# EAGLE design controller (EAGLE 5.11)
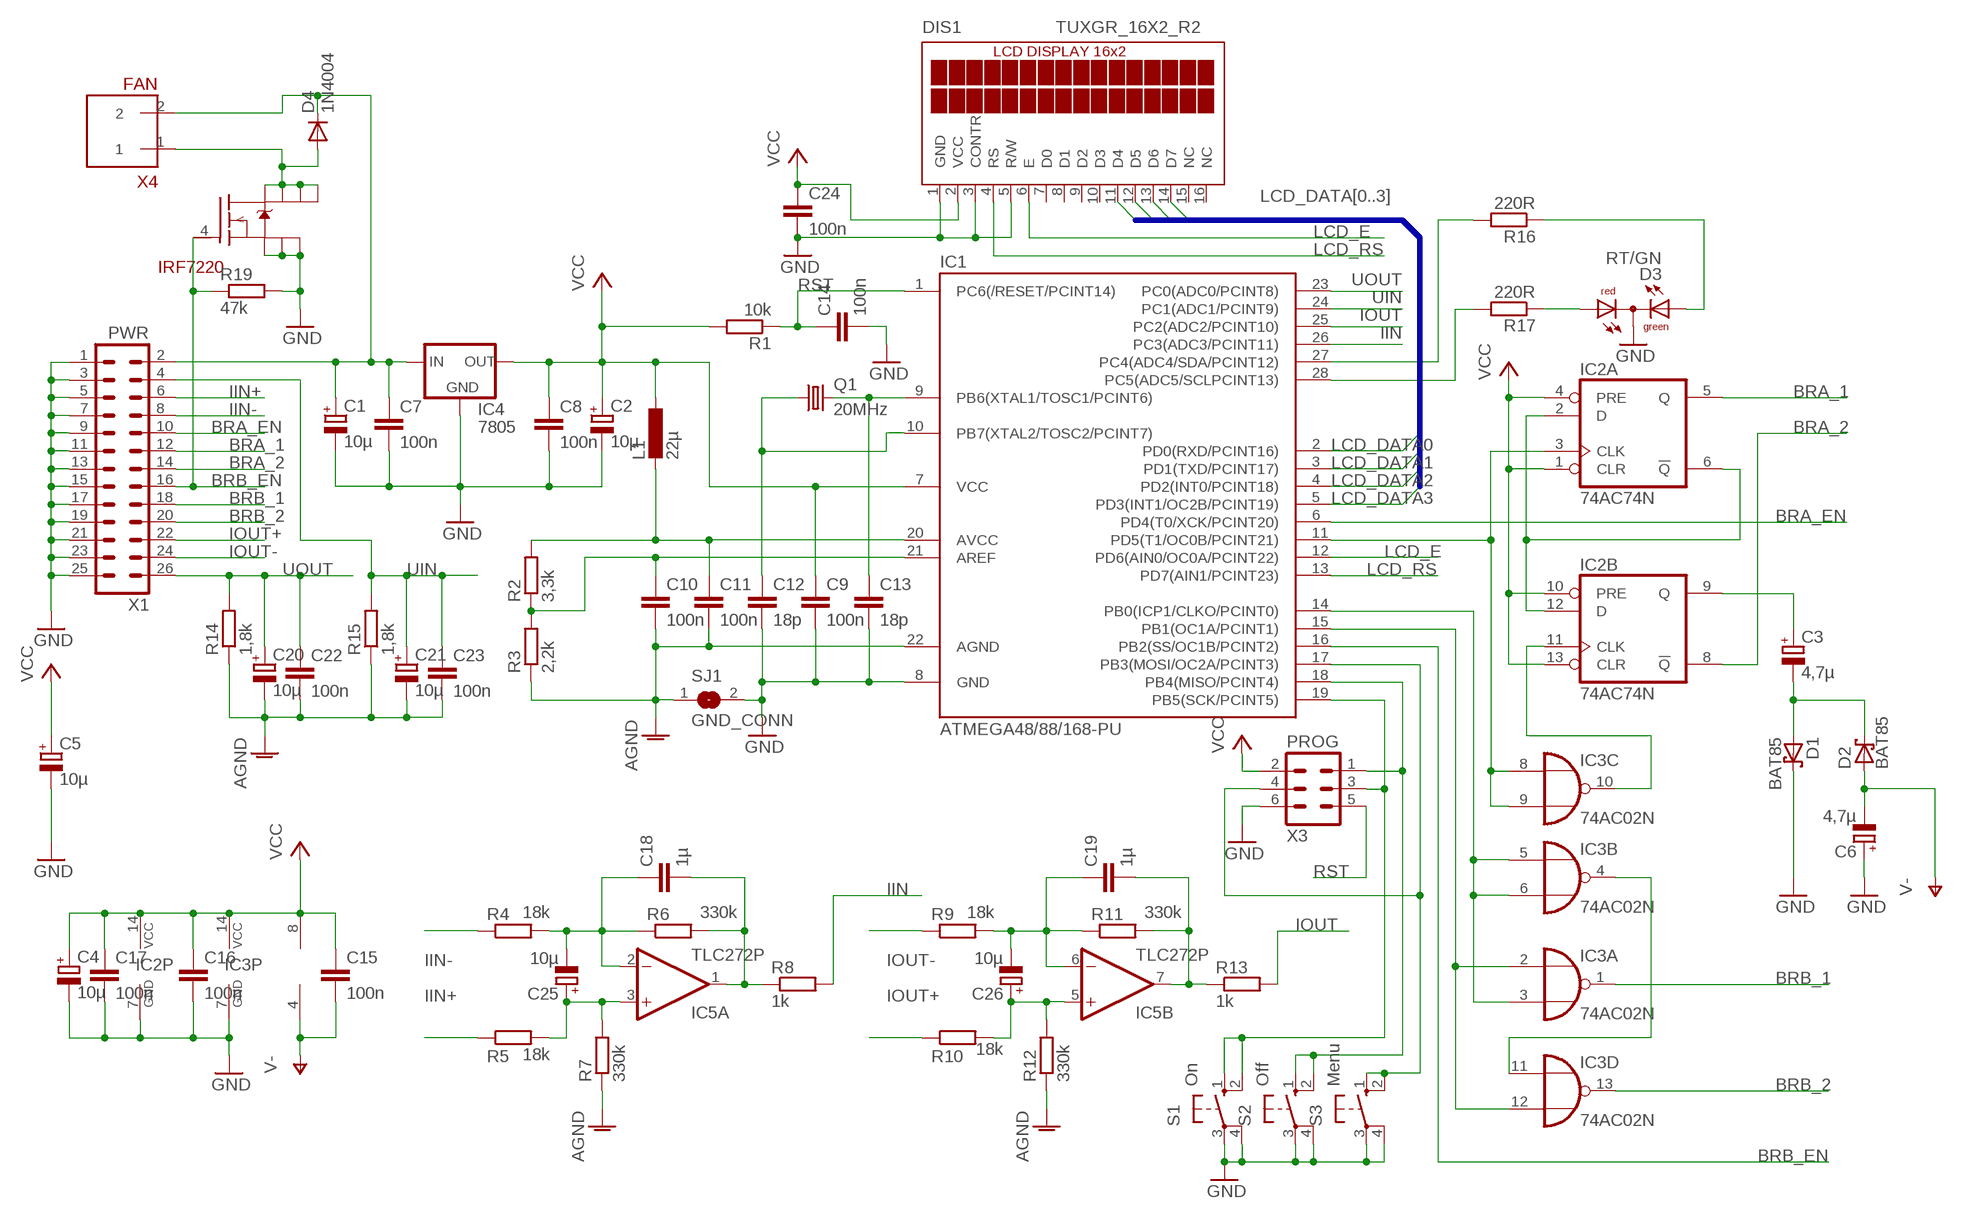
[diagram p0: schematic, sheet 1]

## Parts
C1  10µ  CPOL-EUE2.5-5  [E2,5-5]
C2  10µ  CPOL-EUE2.5-5  [E2,5-5]
C3  4,7µ  CPOL-EUE2.5-5  [E2,5-5]
C4  10µ  CPOL-EUE2.5-5  [E2,5-5]
C5  10µ  CPOL-EUE2.5-5  [E2,5-5]
C6  4,7µ  CPOL-EUE2.5-5  [E2,5-5]
C7  100n  C-EU025-024X044  [C025-024X044]
C8  100n  C-EU025-024X044  [C025-024X044]
C9  100n  C-EU025-024X044  [C025-024X044]
C10  100n  C-EU025-024X044  [C025-024X044]
C11  100n  C-EU025-024X044  [C025-024X044]
C12  18p  C-EU025-024X044  [C025-024X044]
C13  18p  C-EU025-024X044  [C025-024X044]
C14  100n  C-EU025-024X044  [C025-024X044]
C15  100n  C-EU025-024X044  [C025-024X044]
C16  100n  C-EU025-024X044  [C025-024X044]
C17  100n  C-EU025-024X044  [C025-024X044]
C18  1µ  C-EU050-050X075  [C050-050X075]
C19  1µ  C-EU050-050X075  [C050-050X075]
C20  10µ  CPOL-EUE2.5-5  [E2,5-5]
C21  10µ  CPOL-EUE2.5-5  [E2,5-5]
C22  100n  C-EU025-024X044  [C025-024X044]
C23  100n  C-EU025-024X044  [C025-024X044]
C24  100n  C-EU025-024X044  [C025-024X044]
C25  10µ  CPOL-EUE2.5-5  [E2,5-5]
C26  10µ  CPOL-EUE2.5-5  [E2,5-5]
D1  BAT85  BAT42  [DO35-10]
D2  BAT85  BAT42  [DO35-10]
D3  RT/GN  DUOLED5MM  [DUOLED5MM]
D4  1N4004  [DO41-10]
DIS1  TUXGR_16X2_R2  [TUXGR_16X2_R2]
IC1  ATMEGA48/88/168-PU  [DIL28-3]
IC2  74AC74N  [DIL14]
IC3  74AC02N  [DIL14]
IC4  7805  78XXL  [78XXL]
IC5  TLC272P  [DIL08]
L1  22µ  L-EU0207/12  [0207/12]
Q1  20MHz  CRYSTALHC49U-V  [HC49U-V]
R1  10k  R-EU_0207/10  [0207/10]
R2  3,3k  R-EU_0207/10  [0207/10]
R3  2,2k  R-EU_0207/10  [0207/10]
R4  18k  R-EU_0207/10  [0207/10]
R5  18k  R-EU_0207/10  [0207/10]
R6  330k  R-EU_0207/10  [0207/10]
R7  330k  R-EU_0207/10  [0207/10]
R8  1k  R-EU_0207/10  [0207/10]
R9  18k  R-EU_0207/10  [0207/10]
R10  18k  R-EU_0207/10  [0207/10]
R11  330k  R-EU_0207/10  [0207/10]
R12  330k  R-EU_0207/10  [0207/10]
R13  1k  R-EU_0207/10  [0207/10]
R14  1,8k  R-EU_0207/10  [0207/10]
R15  1,8k  R-EU_0207/10  [0207/10]
R16  220R  R-EU_0207/10  [0207/10]
R17  220R  R-EU_0207/10  [0207/10]
R19  47k  R-EU_0207/10  [0207/10]
S1  On  10-XX  [B3F-10XX]
S2  Off  10-XX  [B3F-10XX]
S3  Menu  10-XX  [B3F-10XX]
SJ1  GND_CONN  SJ  [SJ]
T1  IRF7413  [SO-8]
X1  PWR  ML26  [ML26]
X3  PROG  ML6  [ML6]
X4  FAN  KLEMME2X5  [KLEMME2X5]

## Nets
AGND: C10.2 C11.2 C20.- C21.- C22.2 C23.2 IC1.22(AGND) R3.1 R7.1 R12.1 R14.1 R15.1 SJ1.1
BRA_1: IC2.5(A:Q) X1.12
BRA_2: IC2.8(B:!Q) X1.14
BRA_EN: IC1.6(PD4(T0/XCK/PCINT20)) X1.10
BRB_1: IC3.1(A:O) X1.18
BRB_2: IC3.13(D:O) X1.20
BRB_EN: IC1.16(PB2(SS/OC1B/PCINT2)) R19.1 T1.4 X1.16
GND: C1.- C2.- C4.- C5.- C6.+ C7.2 C8.2 C9.2 C12.2 C13.2 C14.2 C16.2 C17.2 C24.2 D1.C D3.K(C) DIS1.1(GND) DIS1.3(CONTR) DIS1.5(R/W) IC1.8(GND) IC2.7(P:GND) IC3.7(P:GND) IC4.GND R19.2 S1.3(P) S1.4(P1) S2.3(P) S2.4(P1) S3.3(P) S3.4(P1) SJ1.2 T1.1 T1.2 T1.3 X1.1 X1.3 X1.5 X1.7 X1.9 X1.11 X1.13 X1.15 X1.17 X1.19 X1.21 X1.23 X1.25 X3.6
IIN: IC1.26(PC3(ADC3/PCINT11)) R8.2
IIN+: R5.1 X1.6
IIN-: R4.1 X1.8
IOUT: IC1.25(PC2(ADC2/PCINT10)) R13.2
IOUT+: R10.1 X1.22
IOUT-: R9.1 X1.24
LCD_DATA0: DIS1.11(D4) IC1.2(PD0(RXD/PCINT16))
LCD_DATA1: DIS1.12(D5) IC1.3(PD1(TXD/PCINT17))
LCD_DATA2: DIS1.13(D6) IC1.4(PD2(INT0/PCINT18))
LCD_DATA3: DIS1.14(D7) IC1.5(PD3(INT1/OC2B/PCINT19))
LCD_E: DIS1.6(E) IC1.12(PD6(AIN0/OC0A/PCINT22))
LCD_RS: DIS1.4(RS) IC1.13(PD7(AIN1/PCINT23))
N$1: C1.+ C7.1 D4.C IC4.IN X1.2 X4.2
N$2: C10.1 IC1.21(AREF) R2.1 R3.2
N$3: C11.1 IC1.20(AVCC) L1.2 R2.2
N$4: IC1.11(PD5(T1/OC0B/PCINT21)) IC2.3(A:CLK) IC3.8(C:I0) IC3.9(C:I1)
N$5: D4.A T1.5 T1.6 T1.7 T1.8 X4.1
N$6: C12.1 IC1.10(PB7(XTAL2/TOSC2/PCINT7)) Q1.1
N$7: C19.2 IC5.7(B:OUT) R11.2 R13.1
N$8: C13.1 IC1.9(PB6(XTAL1/TOSC1/PCINT6)) Q1.2
N$9: IC2.11(B:CLK) IC3.10(C:O)
N$10: IC2.2(A:D) IC2.6(A:!Q) IC2.12(B:D)
N$11: C3.+ IC2.9(B:Q)
N$12: C3.- D1.A D2.C
N$14: C18.1 C25.- IC5.2(A:-IN) R4.2 R6.1
N$15: C18.2 IC5.1(A:OUT) R6.2 R8.1
N$16: C25.+ IC5.3(A:+IN) R5.2 R7.2
N$18: C19.1 C26.- IC5.6(B:-IN) R9.2 R11.1
N$19: C26.+ IC5.5(B:+IN) R10.2 R12.2
N$21: D3.AG R16.1
N$25: IC1.17(PB3(MOSI/OC2A/PCINT3)) S3.1(S) S3.2(S1) X3.4
N$32: IC1.15(PB1(OC1A/PCINT1)) IC3.2(A:I0) IC3.12(D:I1)
N$33: IC1.14(PB0(ICP1/CLKO/PCINT0)) IC3.3(A:I1) IC3.5(B:I0) IC3.6(B:I1)
N$34: IC3.4(B:O) IC3.11(D:I0)
N$35: IC1.18(PB4(MISO/PCINT4)) S2.1(S) S2.2(S1) X3.1
N$36: IC1.19(PB5(SCK/PCINT5)) S1.1(S) S1.2(S1) X3.3
N$37: D3.AR R17.1
N$38: IC1.28(PC5(ADC5/SCLPCINT13)) R17.2
N$39: IC1.27(PC4(ADC4/SDA/PCINT12)) R16.2
RST: C14.1 IC1.1(PC6(/RESET/PCINT14)) R1.1 X3.5
UIN: C21.+ C23.1 IC1.24(PC1(ADC1/PCINT9)) R15.2 X1.4
UOUT: C20.+ C22.1 IC1.23(PC0(ADC0/PCINT8)) R14.2 X1.26
V-: C6.- C15.2 D2.A IC5.4(P:V-)
VCC: C2.+ C4.+ C5.+ C8.1 C9.1 C15.1 C16.1 C17.1 C24.1 DIS1.2(VCC) IC1.7(VCC) IC2.1(A:CLR) IC2.4(A:PRE) IC2.10(B:PRE) IC2.13(B:CLR) IC2.14(P:VCC) IC3.14(P:VCC) IC4.OUT IC5.8(P:V+) L1.1 R1.2 X3.2
Unconnected: DIS1.7(D0) DIS1.8(D1) DIS1.9(D2) DIS1.10(D3) DIS1.15(NC) DIS1.16(NC)

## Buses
LCD_DATA[0..3]

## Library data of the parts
C1-C6 C20 C21 C25 C26 = rcl:CPOL-EU: POLARIZED CAPACITOR, European symbol
C7-C19 C22-C24 = rcl:C-EU: CAPACITOR, European symbol
D1 D2 = diode:BAT42: DIODE
D3 = led:DUOLED5MM: DUO LED 2 colors, 5 mm, round
D4 = diode:1N4004: DIODE
DIS1 = display-lcd:TUXGR_16X2_R2: Tuxgraphics LCD display 16x2 characters reflective, without background light Source: tuxgr_12x2_r2.pdf; OC_FARNELL: unknown; OC_NEWARK: unknown
IC1 = atmega8:ATMEGA48/88/168-PU
IC2 = 74xx-eu:74*74: Dual D type positive edge triggered FLIP FLOP, preset and clear
IC3 = 74xx-eu:74*02: Quad 2-input NOR gate
IC4 = v-reg:78XXL: VOLTAGE REGULATOR
IC5 = linear:TLC272: OP AMP
L1 = rcl:L-EU: INDUCTOR, European symbol
Q1 = andreas:CRYSTAL: CRYSTAL; OC_FARNELL: 1666969; OC_NEWARK: unknown
R1-R17 R19 = rcl:R-EU_: RESISTOR, European symbol
S1-S3 = switch-omron:10-XX: OMRON SWITCH; MPN: B3F-1000; OC_FARNELL: 176432; OC_NEWARK: 36M3542
SJ1 = jumper:SJ: SMD solder JUMPER
T1 = andreas2:IRF7413
X1 = con-ml:ML26: HARTING; OC_FARNELL: unknown; OC_NEWARK: unknown
X3 = con-ml:ML6: HARTING; OC_FARNELL: unknown; OC_NEWARK: unknown
X4 = andreas:KLEMME2X5: Anreihklemme 2-polig, RM5,0

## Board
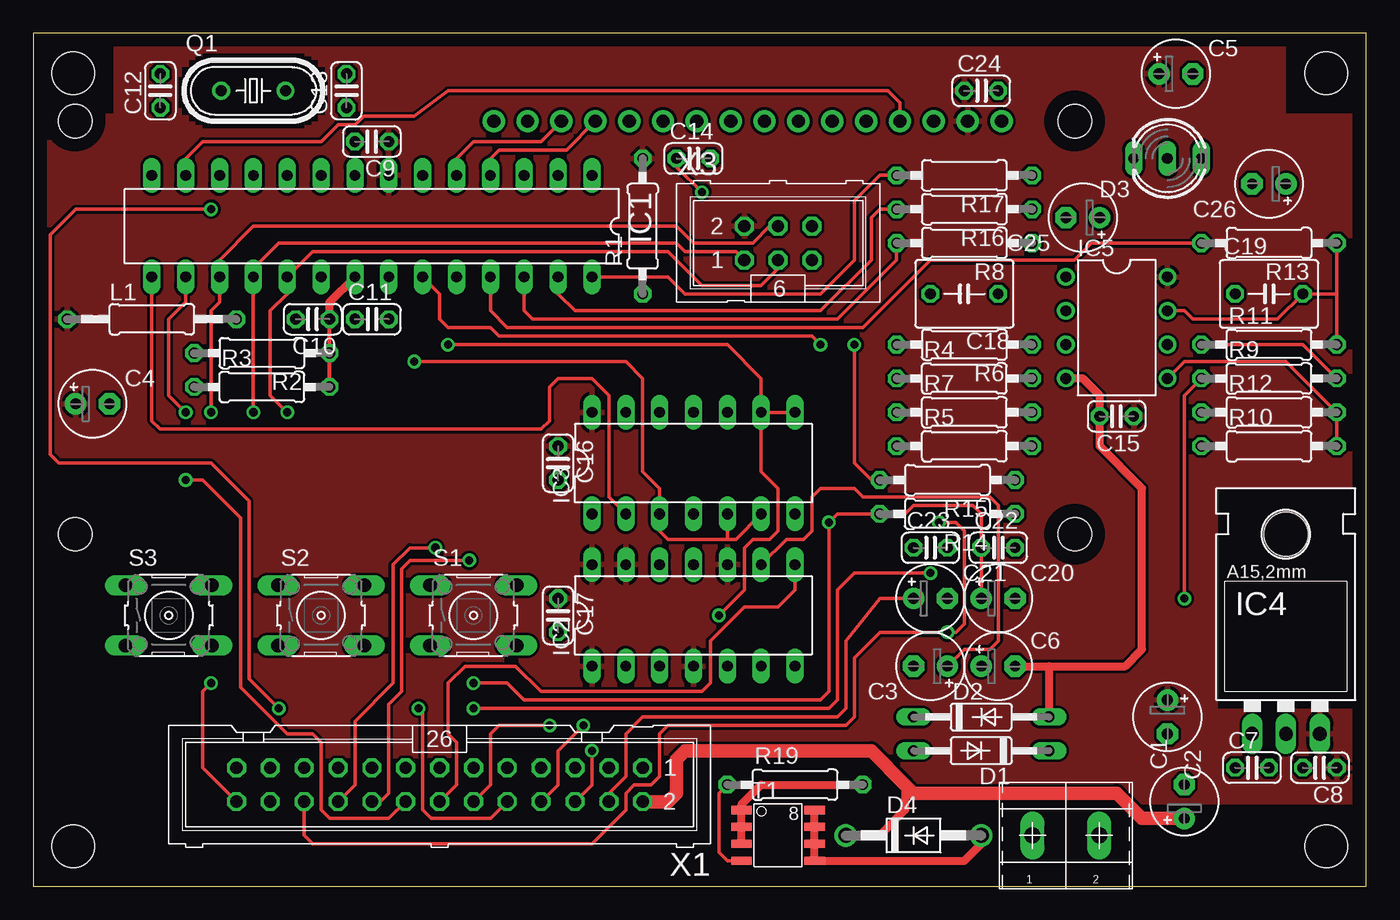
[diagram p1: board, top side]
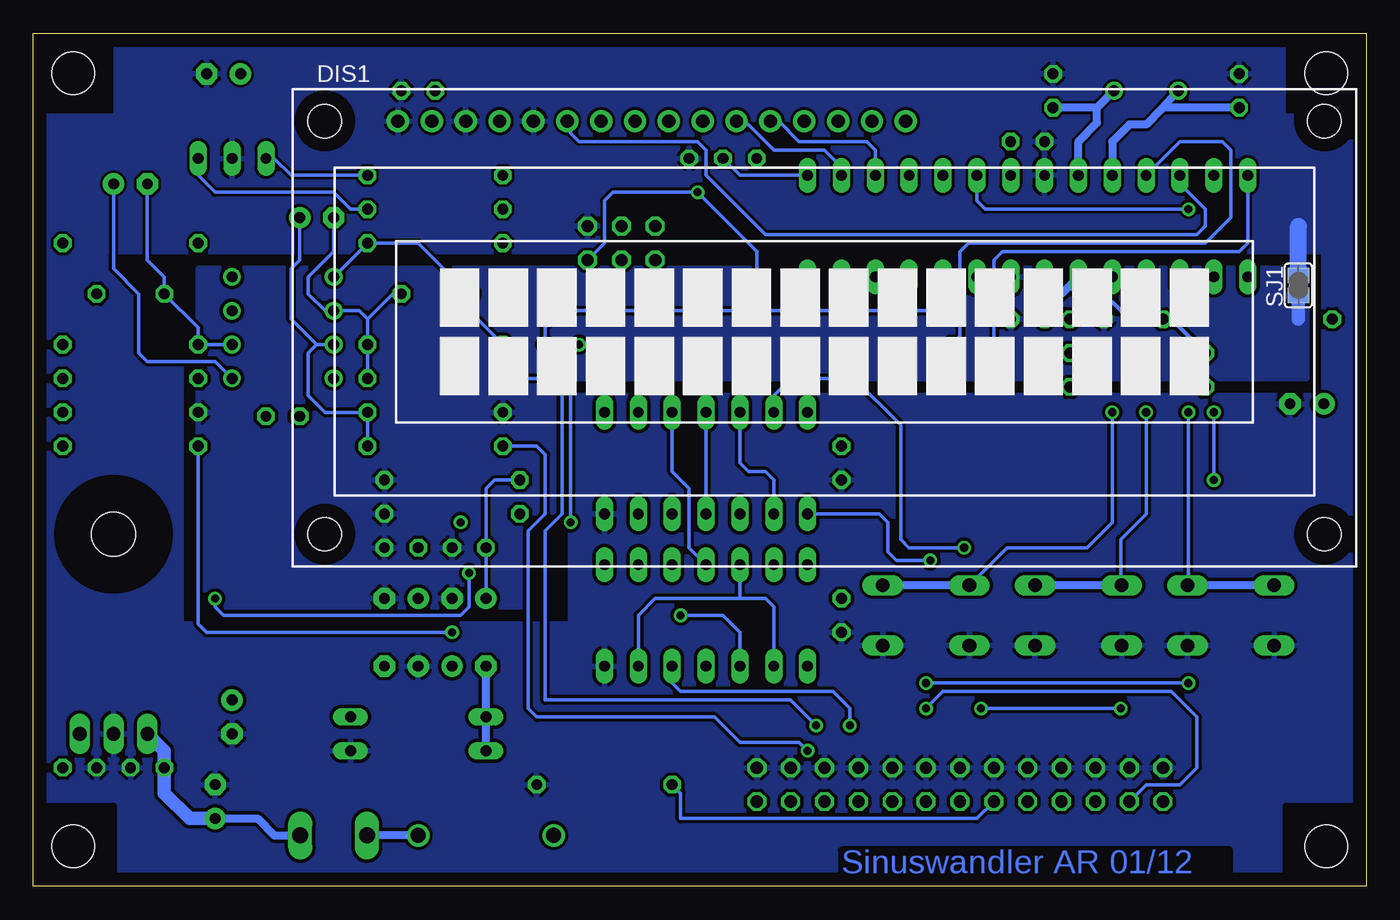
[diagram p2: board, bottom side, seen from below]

Size 100 x 64 mm. Coordinates in mm from the lower left corner, seen from the top.
Outline: 0,0 100,0 100,64 0,64 0,0
Copper layers (1*16): Top 0.035mm / dielectric 1.5mm / Bottom 0.035mm
Design rules "default": minimum track width 10mil, minimum drill 24mil, track to track 8mil, track to pad 8mil, pad to pad 8mil, via to via 8mil, smd to smd 8mil, copper to edge 40mil, drill to drill 8mil, minimum pad ring 10mil, minimum via ring 8mil, stop-mask expansion 4mil, vias tented up to drill 0mil, thermal gap 10mil
Holes 3.2 mm at 3,61 97,61 97,3 3,3
tRestrict: area 88.9,13.3 to 99.1,29.8; area 0,58 to 6,64; area 94,58 to 100,64; area 94,0 to 100,6; area 0,0 to 6,6
bRestrict: area 0,58 to 6,64; area 94,58 to 100,64; area 94,0 to 100,6; area 0,0 to 6,6

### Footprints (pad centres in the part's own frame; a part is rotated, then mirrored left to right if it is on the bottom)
E2,5-5 = drill 0.813 pad 1.6: + -1.27,0 | drill 0.813 pad 1.6 octagon: - 1.27,0
C025-024X044 = drill 0.813 octagon: 1 -1.27,0; 2 1.27,0
C050-050X075 = drill 0.813 octagon: 1 -2.54,0; 2 2.54,0
DO35-10 = drill 0.813 long: A 5.08,0; C -5.08,0
DUOLED5MM = drill 0.813 long: AG -2.54,0; AR 2.54,0; K 0,0
DO41-10 = drill 1.118: A 5.08,0; C -5.08,0
TUXGR_16X2_R2 = drill 1 pad 1.676: 1 -32,15.5; 2 -29.46,15.5; 3 -26.92,15.5; 4 -24.38,15.5; 5 -21.84,15.5; 6 -19.3,15.5; 7 -16.76,15.5; 8 -14.22,15.5; 9 -11.68,15.5; 10 -9.14,15.5; 11 -6.6,15.5; 12 -4.06,15.5; 13 -1.52,15.5; 14 1.02,15.5; 15 3.56,15.5; 16 6.1,15.5 | hole 2.5: -37.5,-15.5; 37.5,-15.5; -37.5,15.5; 37.5,15.5
DIL28-3 = drill 0.813 long: 1 -16.51,-3.81; 2 -13.97,-3.81; 3 -11.43,-3.81; 4 -8.89,-3.81; 5 -6.35,-3.81; 6 -3.81,-3.81; 7 -1.27,-3.81; 8 1.27,-3.81; 9 3.81,-3.81; 10 6.35,-3.81; 11 8.89,-3.81; 12 11.43,-3.81; 13 13.97,-3.81; 14 16.51,-3.81; 15 16.51,3.81; 16 13.97,3.81; 17 11.43,3.81; 18 8.89,3.81; 19 6.35,3.81; 20 3.81,3.81; 21 1.27,3.81; 22 -1.27,3.81; 23 -3.81,3.81; 24 -6.35,3.81; 25 -8.89,3.81; 26 -11.43,3.81; 27 -13.97,3.81; 28 -16.51,3.81
DIL14 = drill 0.813 long: 1 -7.62,-3.81; 2 -5.08,-3.81; 3 -2.54,-3.81; 4 0,-3.81; 5 2.54,-3.81; 6 5.08,-3.81; 7 7.62,-3.81; 8 7.62,3.81; 9 5.08,3.81; 10 2.54,3.81; 11 0,3.81; 12 -2.54,3.81; 13 -5.08,3.81; 14 -7.62,3.81
78XXL = drill 1.016 long: GND 0,-3.81; IN -2.54,-3.81; OUT 2.54,-3.81 | hole 3.302: 0,11.176
DIL08 = drill 0.813 pad 1.27: 1 -3.81,-3.81; 2 -1.27,-3.81; 3 1.27,-3.81; 4 3.81,-3.81; 5 3.81,3.81; 6 1.27,3.81; 7 -1.27,3.81; 8 -3.81,3.81
0207/12 = drill 0.813 octagon: 1 -6.35,0; 2 6.35,0
HC49U-V = drill 0.813: 1 -2.413,0; 2 2.413,0
0207/10 = drill 0.813 octagon: 1 -5.08,0; 2 5.08,0
B3F-10XX = drill 1.016 long: 1 -3.251,2.261; 2 3.251,2.261; 3 -3.251,-2.261; 4 3.251,-2.261
SJ = smd 1.168 x 1.6: 1 -0.762,0; 2 0.762,0
SO-8 = smd 1.524 x 0.61: 1 -2.743,1.27; 2 -2.743,0; 3 -2.743,-1.27; 4 -2.743,-2.54; 5 2.743,-2.54; 6 2.743,-1.27; 7 2.743,0; 8 2.743,1.27
ML26 = drill 0.914 octagon: 1 -15.24,-1.27; 2 -15.24,1.27; 3 -12.7,-1.27; 4 -12.7,1.27; 5 -10.16,-1.27; 6 -10.16,1.27; 7 -7.62,-1.27; 8 -7.62,1.27; 9 -5.08,-1.27; 10 -5.08,1.27; 11 -2.54,-1.27; 12 -2.54,1.27; 13 0,-1.27; 14 0,1.27; 15 2.54,-1.27; 16 2.54,1.27; 17 5.08,-1.27; 18 5.08,1.27; 19 7.62,-1.27; 20 7.62,1.27; 21 10.16,-1.27; 22 10.16,1.27; 23 12.7,-1.27; 24 12.7,1.27; 25 15.24,-1.27; 26 15.24,1.27
ML6 = drill 0.914 octagon: 1 -2.54,-1.27; 2 -2.54,1.27; 3 0,-1.27; 4 0,1.27; 5 2.54,-1.27; 6 2.54,1.27
KLEMME2X5 = drill 1.2 long: 1 0,2.5; 2 0,-2.5

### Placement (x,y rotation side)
C1  86.36,6.35 90 top
C2  85.09,12.7 270 top
C3  67.31,16.51 180 top
C4  4.45,36.2 0 top
C5  85.72,60.96 0 top
C6  72.39,16.51 0 top
C7  91.44,8.89 0 top
C8  96.52,8.89 180 top
C9  25.4,55.88 180 top
C10  20.95,42.55 180 top
C11  25.4,42.55 0 top
C12  9.53,59.69 90 top
C13  23.5,59.69 90 top
C14  49.53,54.61 0 top
C15  81.28,35.26 180 top
C16  39.37,31.75 270 top
C17  39.37,20.32 270 top
C18  69.85,44.45 180 top
C19  92.71,44.45 0 top
C20  72.39,21.59 0 top
C21  67.31,21.59 0 top
C22  72.39,25.4 0 top
C23  67.31,25.4 0 top
C24  71.12,59.69 0 top
C25  78.74,50.16 180 top
C26  92.71,52.7 180 top
D1  71.12,10.16 180 top
D2  71.12,12.7 0 top
D3  85.09,54.61 180 top
D4  66.04,3.81 0 top
DIS1  40.64,41.91 0 bottom
IC1  25.4,49.53 180 top
IC2  49.53,20.32 0 top
IC3  49.53,31.75 0 top
IC4  93.98,15.24 0 top
IC5  81.28,41.91 270 top
L1  8.89,42.55 0 top
Q1  16.51,59.69 0 top
R1  45.72,49.53 90 top
R2  17.14,40.01 180 top
R3  17.14,37.47 0 top
R4  69.85,38.1 0 top
R5  69.85,33.02 0 top
R6  69.85,40.64 180 top
R7  69.85,35.56 0 top
R8  69.85,48.26 180 top
R9  92.71,38.1 0 top
R10  92.71,33.02 0 top
R11  92.71,40.64 0 top
R12  92.71,35.56 0 top
R13  92.71,48.26 180 top
R14  68.58,27.94 180 top
R15  68.58,30.48 180 top
R16  69.85,50.8 180 top
R17  69.85,53.34 180 top
R19  57.15,7.62 0 top
S1  33.02,20.32 0 top
S2  21.59,20.32 0 top
S3  10.16,20.32 0 top
SJ1  5.08,45.09 90 bottom
T1  55.88,4.45 0 top
X1  30.48,7.62 180 top
X3  55.88,48.26 0 top
X4  77.47,3.81 90 top

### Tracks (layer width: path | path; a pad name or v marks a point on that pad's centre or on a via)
AGND
  Bottom 1.016: 5.08,42.55 5.08,44.45
  pour Bottom (isolate 0.254): 4.45,46.35 87.63,46.35 87.63,20.95 60.96,20.95 60.96,38.1 4.45,38.1
BRA_1  (via drill 0.61)
  Top 0.254: X1.12 34.29,7.62 34.29,11.43 34.92,12.06 v38.73,12.06
  Bottom 0.254: IC2.5 52.07,15.24 51.44,14.61 40.01,14.61 38.73,13.34 v38.73,12.06
BRA_2
  Top 0.254: IC2.8 57.15,22.23 55.88,20.95 53.34,20.95 50.8,18.41 50.8,15.24 50.16,14.61 38.1,14.61 36.2,16.51 32.38,16.51 31.11,15.24 31.11,11.43 31.75,10.79 31.75,7.62 X1.14
BRA_EN  (via drill 0.61)
  Top 0.254: v13.34,50.8 3.17,50.8 1.27,48.9 1.27,32.38 1.91,31.75 13.34,31.75 16.19,28.89 16.19,15.56 v18.41,13.34 | X1.10 34.29,5.08 29.84,5.08 29.21,5.71 29.21,13.02 v28.89,13.34
  Bottom 0.254: IC1.6 29.21,51.44 28.57,50.8 v13.34,50.8 | v18.41,13.34 v28.89,13.34
BRB_1  (via drill 0.61)
  Top 0.254: v32.7,24.45 28.26,24.45 27.62,23.81 27.62,14.61 26.67,13.65 26.67,6.99 26.04,6.35 X1.18
  Bottom 0.254: IC3.1 36.51,27.94 35.88,27.3 35.88,25.08 35.24,24.45 v32.7,24.45
BRB_2  (via drill 0.61)
  Top 0.254: v30.16,25.4 28.26,25.4 26.99,24.13 26.99,15.24 24.13,12.38 24.13,7.62 X1.20
  Bottom 0.254: IC3.13 44.45,36.83 43.18,38.1 38.42,38.1 34.92,34.61 34.92,26.04 34.29,25.4 v30.16,25.4
BRB_EN  (via drill 0.61)
  Top 0.254: IC1.16 11.43,43.81 10.16,42.55 10.16,36.83 v11.43,35.56 | T1.4 52.07,1.91 51.44,2.54 51.44,6.99 R19.1 | v11.43,30.48 12.7,30.48 15.56,27.62 15.56,14.92 19.05,11.43 20.95,11.43 21.59,10.79 21.59,5.71 22.23,5.08 26.67,5.08 X1.16
  Bottom 0.254: v11.43,30.48 v11.43,35.56 | X1.16 29.21,5.08 51.44,5.08 51.44,6.99 R19.1
GND
  Top 0.61: T1.3 T1.2 T1.1 53.14,6.15 54.61,7.62 R19.2
  Bottom 1.27: SJ1.2 5.08,49.53
  pour Bottom: -0.64,64.77 -0.64,47.62 100.97,47.62 100.97,64.77
  pour Bottom (isolate 0.254): -0.64,47.62 3.17,47.62 3.17,36.83 59.69,36.83 59.69,19.68 88.9,19.68 88.9,47.62 100.33,47.62 100.33,-0.64 -0.64,-0.64
IIN
  Top 0.254: R8.2 64.77,46.99 60.33,42.55 37.47,42.55 36.83,43.18 IC1.26
IIN+  (via drill 0.61)
  Top 0.254: v41.91,10.16 41.91,7.62 X1.6
  Bottom 0.254: v41.91,10.16 42.55,10.79 46.99,10.79 48.9,12.7 62.23,12.7 62.87,13.34 62.87,26.67 61.59,27.94 61.59,32.38 62.23,33.02 R5.1
IIN-  (via drill 0.61)
  Top 0.254: v41.27,12.06 39.37,10.16 39.37,7.62 X1.8
  Bottom 0.254: v41.27,12.06 43.18,13.97 61.59,13.97 61.59,26.67 60.33,27.94 60.33,37.47 60.96,38.1 R4.1
IOUT
  Top 0.254: IC1.25 34.29,43.18 35.56,41.91 62.23,41.91 67.31,46.99 78.11,46.99 79.38,48.26 R13.2
IOUT+  (via drill 0.61)
  Top 0.254: X1.22 20.32,3.81 20.95,3.17 41.91,3.17 44.45,5.71 44.45,6.99 45.09,7.62 46.35,7.62 46.99,8.26 46.99,11.43 47.62,12.06 60.96,12.06 61.59,12.7 61.59,17.14 63.5,19.05 v68.58,19.05 69.22,19.05 69.85,19.68 69.85,26.67 69.22,27.3 v67.94,27.3
  Bottom 0.254: R10.1 87.63,19.68 87,19.05 v68.58,19.05
IOUT-  (via drill 0.61)
  Top 0.254: v33.02,13.34 59.69,13.34 60.33,13.97 60.33,22.23 61.59,23.5 v67.31,23.5 | R9.1 86.36,36.83 v86.36,21.59
  Bottom 0.254: X1.24 16.51,7.62 13.97,7.62 12.7,8.89 12.7,12.7 14.61,14.61 31.75,14.61 v33.02,13.34 | v67.31,23.5 67.31,20.95 67.94,20.32 85.72,20.32 86.36,20.95 v86.36,21.59
LCD_DATA0
  Bottom 0.254: IC1.2 39.37,53.98 40.64,55.24 44.45,55.24 46.35,57.15 46.98,57.15 DIS1.11
LCD_DATA1
  Bottom 0.254: DIS1.12 44.08,57.41 42.55,55.88 37.47,55.88 36.83,55.24 IC1.3
LCD_DATA2
  Top 0.254: DIS1.13 40.01,55.24 34.92,55.24 34.29,54.61 IC1.4
LCD_DATA3
  Top 0.254: DIS1.14 38.1,55.88 33.02,55.88 31.75,54.61 IC1.5
LCD_E
  Bottom 0.254: DIS1.6 59.69,57.16 59.69,56.52 59.05,55.88 50.16,55.88 49.53,55.24 49.53,53.34 45.09,48.9 12.7,48.9 12.06,49.53 12.06,50.8 13.97,52.7 IC1.12
LCD_RS
  Top 0.254: DIS1.4 65.02,58.8 64.14,59.69 31.11,59.69 28.57,57.78 24.77,57.78 24.13,57.15 22.86,57.15 21.59,55.88 12.7,55.88 11.43,54.61 IC1.13
N$1
  Top 0.61: D4.C 63.5,3.81 65.41,5.71 65.41,7.62
  Top 1.016: X1.2 47.62,6.35 48.26,6.99 48.26,9.53 48.9,10.16 62.87,10.16 65.41,7.62 66.04,6.99 81.28,6.99 83.19,5.08 C1.+
  Bottom 0.61: X4.2 81.92,3.81 83.19,5.08 C1.+
  Bottom 1.016: IC4.IN 90.17,10.16 C7.1 90.17,6.99 88.27,5.08 C1.+
N$2
  Top 0.305: R3.2 R2.1 C10.1
  Top 0.61: C10.1 22.23,43.81 IC1.21
N$3
  Bottom 0.305: IC1.20 19.68,43.81 19.05,43.81 17.78,42.55 L1.2 14.61,42.55 R2.2
  Bottom 0.61: C11.1 24.13,43.18 IC1.20
N$4  (via drill 0.61)
  Top 0.254: IC3.9 54.61,38.1 52.07,40.64 v31.11,40.64 | IC3.9 IC3.8 | IC3.9 54.61,31.11 55.88,29.84 55.88,26.67 55.24,26.04 53.98,26.04 53.34,25.4 53.34,22.23 53.02,21.91 v51.44,20.32
  Bottom 0.254: IC1.11 13.97,55.88 10.79,55.88 10.16,55.24 10.16,50.16 12.06,48.26 29.84,48.26 30.48,47.62 30.48,41.27 v31.11,40.64 | IC2.3 46.99,19.05 48.26,20.32 v51.44,20.32
N$5
  Top 0.61: T1.8 T1.7 T1.6 T1.5 69.85,1.91 71.12,3.17 D4.A
  Bottom 0.61: D4.A X4.1
N$6
  Bottom 0.61: 15.37,58.29 Q1.1 | 15.37,58.29 16.51,57.15 17.78,57.15 19.05,55.88 IC1.10 | C12.1 15.24,58.42 15.37,58.29
N$7
  Top 0.254: IC5.7 86.36,43.18 87,42.55 93.34,42.55 C19.2 97.79,44.45 | 97.79,44.45 R11.2 | 97.79,44.45 R13.1
N$8
  Bottom 0.61: 20.19,58.42 20.19,57.28 21.59,55.88 IC1.9 | 20.19,58.42 Q1.2 | 20.19,58.42 C13.1
N$9
  Bottom 0.254: IC3.10 52.07,31.11 50.8,29.84 50.8,25.4 IC2.11
N$10
  Bottom 0.254: 46.99,21.59 IC2.12 | IC2.6 54.61,20.32 53.34,21.59 46.99,21.59 | IC2.2 44.45,20.95 45.09,21.59 46.99,21.59
N$11
  Top 0.254: C3.+ 69.85,17.78 71.75,17.78 72.39,18.41 72.39,28.57 71.75,29.21 62.23,29.21 61.59,29.84 59.05,29.84 58.42,29.21 58.42,26.67 57.78,26.04 56.52,26.04 IC2.9
N$12
  Bottom 0.61: D1.A D2.C C3.-
N$14
  Bottom 0.254: C18.1 73.03,44.45 74.93,42.55 | 74.93,42.55 R6.1 R4.2 | 74.93,42.55 75.56,43.18 IC5.2 78.11,43.18 79.38,44.45 79.38,45.72 77.47,47.62 C25.-
N$15
  Bottom 0.254: IC5.1 R8.1 71.12,48.26 C18.2 67.31,43.18 R6.2
N$16
  Bottom 0.254: 78.74,40.64 IC5.3 | 78.74,40.64 79.38,40.01 79.38,36.83 78.11,35.56 R7.2 R5.2 | C25.+ 80.01,46.99 80.64,46.35 80.64,42.55 78.74,40.64
N$18
  Top 0.254: R11.1 95.25,40.64 R9.2
  Bottom 0.254: IC5.6 R11.1 87.63,41.91 C19.1 90.17,45.72 91.44,46.99 C26.-
N$19
  Top 0.254: IC5.5 86.36,39.37 93.98,39.37 97.16,36.2 R12.2 R10.2
  Bottom 0.254: C26.+ 93.98,46.35 92.08,44.45 92.08,40.01 91.44,39.37 86.36,39.37 IC5.5
N$21
  Bottom 0.254: R16.1 76.2,50.8 77.47,52.07 86.36,52.07 87.63,53.34 D3.AG
N$25  (via drill 0.61)
  Top 0.254: X3.4 55.24,49.53 53.98,48.26 49.53,48.26 48.26,49.53 16.51,49.53 13.97,46.99 IC1.17 13.97,43.81 13.34,43.18 v13.34,35.56
  Bottom 0.254: v13.34,35.56 13.34,22.66 S3.2
  Bottom 0.61: S3.1 S3.2
N$32
  Top 0.254: IC1.15 8.89,34.92 9.53,34.29 38.1,34.29 38.73,34.92 38.73,37.47 39.37,38.1 41.91,38.1 43.18,36.83 43.18,29.21 IC3.2
  Bottom 0.254: IC3.12 46.99,31.75 46.35,31.11 45.09,31.11 44.45,30.48 IC3.2
N$33  (via drill 0.61)
  Top 0.254: v28.57,39.37 44.45,39.37 45.72,38.1 45.72,31.11 46.99,29.84 IC3.3 46.99,26.67 47.62,26.04 52.07,26.04 | IC3.6 52.7,26.04 52.07,26.04 | 52.07,26.04 IC3.5
  Bottom 0.254: IC1.14 8.89,48.26 9.53,47.62 27.3,47.62 27.94,46.99 27.94,40.01 v28.57,39.37
N$34
  Bottom 0.254: IC3.4 IC3.11
N$35  (via drill 0.61)
  Top 0.254: X3.1 52.7,47.62 48.9,47.62 48.26,48.26 18.41,48.26 16.51,46.35 IC1.18 v16.51,35.56
  Bottom 0.254: v16.51,35.56 16.51,27.94 18.41,26.04 18.41,22.66 S2.1
  Bottom 0.61: S2.1 S2.2
N$36  (via drill 0.61)
  Top 0.254: X3.3 55.88,46.35 54.61,45.09 50.16,45.09 47.62,47.62 20.95,47.62 IC1.19 19.05,44.45 17.78,43.18 17.78,36.83 v19.05,35.56
  Bottom 0.254: v19.05,35.56 19.05,27.3 20.95,25.4 26.95,25.4 S1.1
  Bottom 0.61: S1.1 S1.2
N$37
  Bottom 0.254: D3.AR 81.92,54.61 80.64,53.34 R17.1
N$38
  Top 0.254: R17.2 63.5,53.34 61.59,51.44 61.59,46.99 59.05,44.45 48.9,44.45 47.62,45.72 IC1.28
N$39
  Top 0.254: IC1.27 39.37,44.45 40.64,43.18 59.05,43.18 62.87,46.99 62.87,50.16 63.5,50.8 R16.2
RST  (via drill 0.61)
  Top 0.254: C14.1 48.26,53.98 v50.16,52.07
  Bottom 0.254: IC1.1 46.99,53.34 C14.1 | X3.5 57.15,48.26 57.15,51.44 56.52,52.07 v50.16,52.07 45.72,47.62 R1.1
UIN  (via drill 0.61)
  Top 0.254: C21.+ 63.5,21.59 60.96,18.41 60.96,13.34 60.33,12.7 45.72,12.7 44.45,11.43 44.45,8.26 43.18,6.99 X1.4 | v61.59,40.64 61.59,31.75 62.87,30.48 R15.2
  Bottom 0.254: v61.59,40.64 61.59,41.91 60.33,43.18 33.02,43.18 31.75,44.45 IC1.24 | R15.2 65.41,30.48 66.04,29.84 C23.1 C21.+
UOUT  (via drill 0.61)
  Top 0.254: X1.26 12.7,8.89 12.7,14.61 v13.34,15.24 | v33.02,15.24 35.56,15.24 36.83,13.97 59.05,13.97 59.69,14.61 59.69,26.04 v59.69,27.3 60.33,27.94 R14.2 65.41,27.94 66.04,28.57 70.48,28.57 71.12,27.94 C22.1 C20.+ | IC1.23 30.48,44.45 30.48,42.55 31.11,41.91 34.29,41.91 34.92,41.27 58.42,41.27 v59.05,40.64
  Bottom 0.254: v13.34,15.24 v33.02,15.24 | v59.05,40.64 59.69,40.01 v59.69,27.3
V-
  Top 0.61: C6.- 76.2,16.51 | IC5.4 78.74,38.1 80.01,36.83 C15.2 80.01,33.02 83.19,29.84 83.19,17.78 81.92,16.51 76.2,16.51 | 76.2,16.51 D2.A
VCC
  pour Top: -0.64,64.77 100.33,64.77 100.33,6.35 45.72,6.35 45.72,-0.64 -0.64,-0.64

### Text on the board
Bottom: Sinuswandler AR 01/12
